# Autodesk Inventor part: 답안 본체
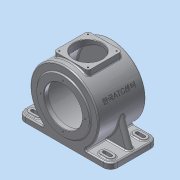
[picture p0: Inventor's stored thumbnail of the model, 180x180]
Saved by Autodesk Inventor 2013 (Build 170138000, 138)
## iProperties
Created: 2015-06
Part Number: 답안 본체
Material: 알루미늄 6061
Document SubType Name: Modeling
Designer: Administrator
Density: 2.71 g/cm^3
Mass: 3263.9 g
Surface Area: 2330.7 cm^2
Volume: 1204.39 cm^3
Author: Administrator
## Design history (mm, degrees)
sketch "스케치1"
  geometry: C1 r 85 at (0, 0); 1 further point
  constraints: 1 centre point, 1 coincident
  dimensions: "d0" = 170 diameter of C1
extrude "돌출1" new body sketch "스케치1" stored distance "d2" = 118; taper "d3" = 0 deg
sketch "스케치2"
  geometry: L1 (0, 0)-(0, -85); L2 (-115, -85)-(115, -85); L3 (115, -85)-(115, -71); L4 (115, -71)-(-115, -71); L5 (-115, -71)-(-115, -85)
  constraints: 10 end point, 3 perpendicular, 1 midpoint, 1 parallel, 1 vertical
  dimensions: "d4" = 85 distance of L1.end L1.start; "d5" = 230 distance of L2.start L2.end; "d6" = 14 distance of L2.end L3.end
extrude "돌출2" join sketch "스케치2" stored distance "d7" = 118; taper "d8" = 0 deg
sketch "스케치3"
  geometry: C1 r 65 at (0, 0); A1 r 85 centre (0, 0) between (46.733, -71) and (-46.733, -71) reference
  constraints: 1 centre point, 1 coincident
  dimensions: "d9" = 130 diameter of C1
extrude "돌출3" join sketch "스케치3" distance "d10" = 13; taper "d11" = 0 deg
sketch "스케치4"
  geometry: C1 r 65 at (0, 0); A1 r 85 centre (0, 0) between (46.733, -71) and (-46.733, -71) reference
  constraints: 1 centre point, 1 coincident
  dimensions: "d12" = 130 diameter of C1
extrude "돌출4" join sketch "스케치4" distance "d14" = 3; taper "d15" = 0 deg
sketch "스케치5"
  geometry: C1 r 65 at (0, 0) reference; C2 r 47.5 at (0, 0)
  constraints: 1 centre point, 1 coincident
  dimensions: "d16" = 95 diameter of C2
extrude "돌출5" cut sketch "스케치5" distance "d17" = 11; taper "d18" = 0 deg
sketch "스케치6"
  geometry: C1 r 47.5 at (0, 0) reference; C2 r 77 at (0, 0)
  constraints: 1 centre point, 1 coincident
  dimensions: "d19" = 154 diameter of C2
extrude "돌출6" cut sketch "스케치6" distance "d21" = 102; taper "d22" = 0 deg
sketch "스케치7"
  geometry: C1 r 77 at (0, 0) reference; C2 r 31 at (0, 0)
  constraints: 1 centre point, 1 coincident
  dimensions: "d23" = 62 diameter of C2
extrude "돌출7" join sketch "스케치7" distance "d24" = 3.5; taper "d25" = -25 deg
sketch "스케치8"
  geometry: C1 r 29.368 at (0, 0) reference; C2 r 23.5 at (0, 0)
  constraints: 1 centre point, 1 coincident
  dimensions: "d26" = 47 diameter of C2
extrude "돌출8" cut sketch "스케치8" distance "d27" = 14; taper "d28" = 0 deg
sketch "스케치9"
  geometry: C1 r 23.5 at (0, 0) reference; C2 r 15 at (0, 0)
  constraints: 1 centre point, 1 coincident
  dimensions: "d29" = 30 diameter of C2
extrude "돌출9" cut sketch "스케치9" distance "d31" = 3; taper "d32" = 0 deg
sketch "스케치10"
  geometry: L1 (-109, -71)-(-84.87, -4.703); L2 (-115, -85)-(-115, -71) reference; L3 (-115, -71)-(-46.733, -71) reference; A1 r 85 centre (0, 0) between (46.733, -71) and (-46.733, -71) reference; 1 further point
  constraints: 2 end point, 1 point on circle, 1 point on line
  dimensions: "d33" = 6 distance from line of L2 L1.start; "d34" = 110 deg angle of L3 L1
feature "리브1" sketch "스케치10" dims "d35" = 1, "d36" = 15, "d37" = 0, "d38" = 0, "d39" = 1, "d40" = 1
sketch "스케치11"
  geometry: L1 (0, 118)-(68.267, 118) reference; L2 (-16.934, 8)-(-16.934, 110) reference; L3 (-16.934, 110)-(-76.533, 110) reference; L4 (-76.533, 110)-(-76.533, 8) reference; L5 (-76.533, 8)-(-16.934, 8) reference; L6 (68.267, 118)-(68.267, 0) reference; L7 (68.267, 0)-(0, 0) reference; L8 (0, 51.5)-(0, 0) reference; L9 (62.267, 51.5)-(0, 51.5) reference; L10 (62.267, 66.5)-(62.267, 51.5) reference; L11 (0, 66.5)-(62.267, 66.5) reference; L12 (0, 118)-(0, 66.5) reference; L13 (-93.467, 118)-(0, 118) reference; L14 (-93.467, 66.5)-(-93.467, 118) reference; L15 (-155.733, 66.5)-(-93.467, 66.5) reference; L16 (-155.733, 51.5)-(-155.733, 66.5) reference; L17 (-93.467, 51.5)-(-155.733, 51.5) reference; L18 (-93.467, 0)-(-93.467, 51.5) reference; L19 (-93.467, 0)-(-161.733, 0) reference; L20 (-161.733, 0)-(-161.733, 118) reference; L21 (-161.733, 118)-(-93.467, 118) reference; L22 (0, 118)-(68.267, 118) reference; L23 (0, 0)-(-93.467, 0) reference; L24 (-143.733, 100)-(50.267, 100); L25 (50.267, 100)-(50.267, 18); L26 (50.267, 18)-(-143.733, 18); L27 (-143.733, 18)-(-143.733, 100); L28 (50.267, 100)-(-143.733, 18); L29 (50.267, 18)-(-143.733, 100); L30 (34.267, 91)-(50.267, 91); L31 (34.267, 109)-(50.267, 109); A1 r 9 centre (50.267, 100) between (50.267, 91) and (50.267, 109); A2 r 9 centre (34.267, 100) between (34.267, 91) and (34.267, 109); 2 further points
  constraints: 16 end point, 4 point on circle, 3 parallel, 2 centre point, 2 coincident, 2 point on line, 2 tangent, 1 horizontal, 1 midpoint, 1 perpendicular
  dimensions: "d41" = 18 distance between parallel lines of L1 L24; "d42" = 194 distance of L24.start L24.end; "d43" = 18 diameter of A1; "d44" = 18 diameter of A2; "d45" = 16 distance of A2.centre L24.end
extrude "돌출10" join sketch "스케치11" distance "d46" = 3; taper "d47" = 0 deg
sketch "스케치12"
  geometry: L1 (34.267, 91)-(50.267, 91) reference; L2 (34.267, 96)-(50.267, 96); L3 (34.267, 104)-(50.267, 104); A1 r 9 centre (50.267, 100) between (50.267, 91) and (50.267, 109) reference; A2 r 9 centre (34.267, 100) between (34.267, 109) and (34.267, 91) reference; A3 r 4 centre (34.267, 100) between (34.267, 96) and (34.267, 104); A4 r 4 centre (50.267, 100) between (50.267, 96) and (50.267, 104); 1 further point
  constraints: 4 end point, 4 point on circle, 2 centre point, 2 coincident, 2 parallel, 2 tangent
  dimensions: "d48" = 8 diameter of A3; "d49" = 8 diameter of A4
extrude "돌출11" cut sketch "스케치12" stored distance "d50" = 3; taper "d51" = 0 deg
sketch "스케치13"
  geometry: L1 (212, 104)-(196, 104) reference; L2 (196, 96)-(212, 96) reference; L3 (212, 91)-(196, 91) reference; L4 (196, 109)-(212, 109) reference; L5 (144.799, 8)-(144.799, 110) reference; L6 (144.799, 110)-(85.201, 110) reference; L7 (85.201, 110)-(85.201, 8) reference; L8 (85.201, 8)-(144.799, 8) reference; L9 (230, 118)-(230, 0) reference; L10 (230, 0)-(161.733, 0) reference; L11 (161.733, 51.5)-(161.733, 0) reference; L12 (224, 51.5)-(161.733, 51.5) reference; L13 (224, 66.5)-(224, 51.5) reference; L14 (161.733, 66.5)-(224, 66.5) reference; L15 (161.733, 118)-(161.733, 66.5) reference; L16 (68.267, 118)-(161.733, 118) reference; L17 (68.267, 66.5)-(68.267, 118) reference; L18 (6, 66.5)-(68.267, 66.5) reference; L19 (6, 51.5)-(6, 66.5) reference; L20 (68.267, 51.5)-(6, 51.5) reference; L21 (68.267, 0)-(68.267, 51.5) reference; L22 (68.267, 0)-(0, 0) reference; L23 (0, 0)-(0, 118) reference; L24 (0, 118)-(68.267, 118) reference; L25 (161.733, 118)-(230, 118) reference; L26 (161.733, 0)-(68.267, 0) reference; L27 (18, 100)-(212, 100) reference; L28 (212, 18)-(18, 100) reference; L29 (18, 18)-(18, 100) reference; L30 (212, 18)-(18, 18) reference; L31 (212, 100)-(212, 18) reference; L32 (18, 9)-(34, 9); L33 (18, 27)-(34, 27); L34 (18, 91)-(34, 91); L35 (34, 109)-(18, 109); L36 (212, 27)-(196, 27); L37 (212, 9)-(196, 9); A1 r 4 centre (196, 100) between (196, 104) and (196, 96) reference; A2 r 4 centre (212, 100) between (212, 96) and (212, 104) reference; A3 r 9 centre (196, 100) between (196, 109) and (196, 91) reference; A4 r 9 centre (212, 100) between (212, 91) and (212, 109) reference; A5 r 9 centre (212, 18) between (212, 27) and (212, 9); A6 r 9 centre (196, 18) between (196, 27) and (196, 9); A7 r 9 centre (18, 18) between (18, 9) and (18, 27); A8 r 9 centre (18, 100) between (18, 91) and (18, 109); A9 r 9 centre (34, 100) between (34, 91) and (34, 109); A10 r 9 centre (34, 18) between (34, 9) and (34, 27); 1 further point
  constraints: 12 end point, 12 point on circle, 7 tangent, 6 centre point, 5 point on line, 3 coincident, 2 parallel, 2 perpendicular, 1 vertical alignment
  dimensions: "d52" = 18 diameter of A5; "d53" = 18 diameter of A6; "d54" = 18 diameter of A7; "d55" = 18 diameter of A8; "d56" = 18 diameter of A9; "d57" = 18 diameter of A10; "d58" = 16 distance of A10.centre A7.centre; "d59" = 16 distance of A9.centre L27.start
extrude "돌출12" join sketch "스케치13" distance "d60" = 3; taper "d61" = 0 deg
sketch "스케치14"
  geometry: L1 (50.267, 9)-(34.267, 9) reference; L2 (34.267, 27)-(50.267, 27) reference; L3 (-143.733, 27)-(-127.733, 27) reference; L4 (-127.733, 9)-(-143.733, 9) reference; L5 (-143.733, 109)-(-127.733, 109) reference; L6 (-127.733, 91)-(-143.733, 91) reference; L7 (50.267, 104)-(34.267, 104) reference; L8 (34.267, 96)-(50.267, 96) reference; L9 (50.267, 91)-(34.267, 91) reference; L10 (34.267, 109)-(50.267, 109) reference; L11 (-16.934, 8)-(-16.934, 110) reference; L12 (-16.934, 110)-(-76.533, 110) reference; L13 (-76.533, 110)-(-76.533, 8) reference; L14 (-76.533, 8)-(-16.934, 8) reference; L15 (68.267, 118)-(68.267, 0) reference; L16 (68.267, 0)-(0, 0) reference; L17 (0, 51.5)-(0, 0) reference; L18 (62.267, 51.5)-(0, 51.5) reference; L19 (62.267, 66.5)-(62.267, 51.5) reference; L20 (0, 66.5)-(62.267, 66.5) reference; L21 (0, 118)-(0, 66.5) reference; L22 (-93.467, 118)-(0, 118) reference; L23 (-93.467, 66.5)-(-93.467, 118) reference; L24 (-155.733, 66.5)-(-93.467, 66.5) reference; L25 (-155.733, 51.5)-(-155.733, 66.5) reference; L26 (-93.467, 51.5)-(-155.733, 51.5) reference; L27 (-93.467, 0)-(-93.467, 51.5) reference; L28 (-93.467, 0)-(-161.733, 0) reference; L29 (-161.733, 0)-(-161.733, 118) reference; L30 (-161.733, 118)-(-93.467, 118) reference; L31 (0, 118)-(68.267, 118) reference; L32 (0, 0)-(-93.467, 0) reference; L33 (-143.733, 96)-(-127.733, 96); L34 (-127.733, 104)-(-143.733, 104); L35 (-143.733, 22)-(-127.733, 22); L36 (-127.733, 14)-(-143.733, 14); L37 (34.267, 14)-(50.267, 14); L38 (34.267, 22)-(50.267, 22); A1 r 9 centre (34.267, 18) between (34.267, 27) and (34.267, 9) reference; A2 r 9 centre (50.267, 18) between (50.267, 9) and (50.267, 27) reference; A3 r 9 centre (-127.733, 18) between (-135.733, 22.123) and (-135.733, 13.877) reference; A4 r 9 centre (-143.733, 18) between (-135.733, 13.877) and (-135.733, 22.123) reference; A5 r 9 centre (-143.733, 18) between (-143.733, 27) and (-143.733, 9) reference; A6 r 9 centre (-127.733, 18) between (-127.733, 9) and (-127.733, 27) reference; A7 r 9 centre (-143.733, 100) between (-143.733, 109) and (-143.733, 91) reference; A8 r 9 centre (-127.733, 100) between (-127.733, 91) and (-127.733, 109) reference; A9 r 4 centre (34.267, 100) between (34.267, 104) and (34.267, 96) reference; A10 r 4 centre (50.267, 100) between (50.267, 96) and (50.267, 104) reference; A11 r 9 centre (34.267, 100) between (34.267, 109) and (34.267, 91) reference; A12 r 9 centre (50.267, 100) between (50.267, 91) and (50.267, 109) reference; A13 r 4 centre (50.267, 18) between (50.267, 14) and (50.267, 22); A14 r 4 centre (34.267, 18) between (34.267, 14) and (34.267, 22); A15 r 4 centre (-127.733, 18) between (-127.733, 22) and (-127.733, 14); A16 r 4 centre (-143.733, 18) between (-143.733, 22) and (-143.733, 14); A17 r 4 centre (-127.733, 100) between (-127.733, 96) and (-127.733, 104); A18 r 4 centre (-143.733, 100) between (-143.733, 96) and (-143.733, 104); 1 further point
  constraints: 12 end point, 12 point on circle, 8 tangent, 6 centre point, 6 coincident, 4 parallel
  dimensions: "d62" = 8 diameter of A13; "d63" = 8 diameter of A14; "d64" = 8 diameter of A15; "d65" = 8 diameter of A16; "d66" = 8 diameter of A17; "d67" = 8 diameter of A18
extrude "돌출13" cut sketch "스케치14" distance "d68" = 3; taper "d69" = 0 deg; dims "d70" = 14, "d71" = 0
fillet "모깎기11" dims "d120" = 3
fillet "모깎기1" dims "d72" = 18
fillet "모깎기2" dims "d73" = 7.5
fillet "모깎기3" dims "d74" = 3
chamfer "모따기1" distance "d75" = 1; stored, may be unused: second distance "d76" = 2, angle "d77" = 45 deg
sketch "스케치15"
  geometry: C1 r 65 at (0, 0) reference; 1 further point
  constraints: 1 vertical alignment
  dimensions: "d78" = 55 distance of C1.centre point (0, 55)
hole "구멍1" sketch "스케치15" at (0, 55) diameter "d79" = 3.459; stored, may be unused: countersink angle "d83" = 90 deg, drill point angle "d85" = 118 deg; dims "d80" = 11, "d81" = 4, "d82" = 2, "d84" = 11
node "작업 평면1"
sketch "스케치16"
  geometry: L1 (-139.5, 16.5)-(-54.5, 16.5); L2 (-54.5, 16.5)-(-54.5, 101.5); L3 (-54.5, 101.5)-(-139.5, 101.5); L4 (-139.5, 101.5)-(-139.5, 16.5); L5 (-139.5, 16.5)-(-54.5, 101.5); L6 (-54.5, 16.5)-(-139.5, 101.5); 1 further point
  constraints: 12 end point, 2 midpoint, 2 parallel, 1 horizontal, 1 perpendicular
  dimensions: "d90" = 85 distance of L3.end L2.end; "d91" = 85 distance of L2.end L1.end
extrude "돌출14" join sketch "스케치16" stored distance "d92" = 3; taper "d93" = 0 deg
sketch "스케치17"
  geometry: C1 r 35 at (97, -59); 1 further point
  constraints: 1 centre point, 1 coincident
  dimensions: "d94" = 70 diameter of C1
extrude "돌출15" cut sketch "스케치17" stored distance "d95" = 3; taper "d96" = 0 deg
fillet "모깎기4" dims "d97" = 7
fillet "모깎기5" dims "d98" = 3
fillet "모깎기6" dims "d99" = 3
node "작업 평면5"
  node "작업 평면4"
sketch "스케치18"
  geometry: 2 further points
  constraints: 1 coincident, 1 other
feature "엠보싱1" sketch "스케치18" dims "d0" = 170, "d102" = 0.5, "d103" = 0
chamfer "모따기2" distance "d104" = 1; stored, may be unused: second distance "d105" = 2, angle "d106" = 45 deg
sketch "스케치19"
  geometry: L1 (61.5, -94.5)-(132.5, -94.5); L2 (132.5, -94.5)-(132.5, -23.5); L3 (132.5, -23.5)-(61.5, -23.5); L4 (61.5, -23.5)-(61.5, -94.5); L5 (61.5, -94.5)-(132.5, -23.5); L6 (132.5, -94.5)-(61.5, -23.5); C1 r 36 at (97, -59) reference; A1 r 7 centre (132.5, -23.5) between (139.5, -23.5) and (132.5, -16.5) reference; 4 further points
  constraints: 12 end point, 4 coincident, 2 midpoint, 2 parallel, 1 horizontal, 1 perpendicular
  dimensions: "d107" = 71 distance of L3.end L2.end (derived); "d108" = 71 distance of L2.end L1.end (derived)
hole "구멍2" sketch "스케치19" at (61.5, -23.5), (61.5, -94.5), (132.5, -94.5), (132.5, -23.5) diameter "d109" = 3.459; stored, may be unused: countersink angle "d113" = 90 deg, drill point angle "d115" = 118 deg; dims "d110" = 10, "d111" = 4, "d112" = 2, "d114" = 13
fillet "모깎기7" dims "d116" = 3
fillet "모깎기8" dims "d117" = 3
fillet "모깎기9" dims "d118" = 0.3
fillet "모깎기10" dims "d119" = 3
node "솔리드1"
mirror "대칭1"
pattern_circular "원형 패턴1" dims angle "d87" = 360 deg
node "절단 모서리 투영1"
node "절단 모서리 투영2"
node "절단 모서리 투영3"
other parameters: "d89" = -173, "d101" = -65 deg
